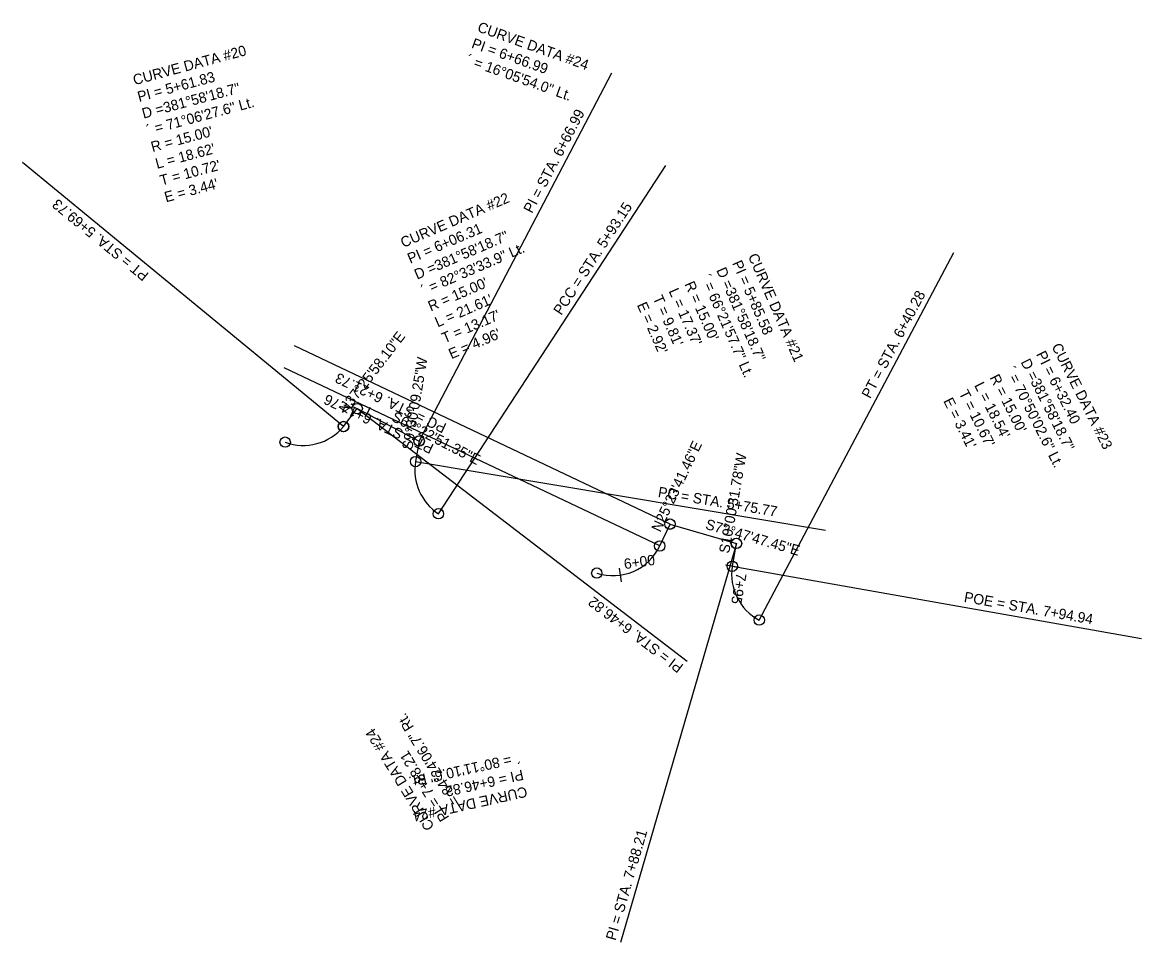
# Model space of a CAD drawing. Extents: x 1158784 to 1165006, y 610007 to 611539.
# Drawn here: x 1158783.8 to 1159106.9, y 611273.6 to 611539.2 of the extents above; entities that cross this region are included whole.
import ezdxf

# ---------------------------------------------------------------- set-up
doc = ezdxf.new("R2010")
doc.units = 0
for name, color, linetype in [('D_Roadway_Centerline', 7, 'Continuous'), ('D_Roadway_Centerline_Bearings', 7, 'Continuous'), ('D_Roadway_Centerline_CurveData', 7, 'Continuous'), ('D_Roadway_Centerline_Flags', 7, 'Continuous'), ('D_Roadway_Centerline_Text', 7, 'Continuous')]:
    doc.layers.add(name, color=color, linetype=linetype)

msp = doc.modelspace()

# ---------------------------------------------------------------- linework, layer by layer
at = {"layer": 'D_Roadway_Centerline'}
for p, q in [((1158876.47, 611422.53), (1158880.44, 611427.72)), ((1158880.44, 611427.72), (1158898.32, 611418.36)), ((1158898.29, 611418.38), (1158897.3, 611412.42)), ((1158967.77, 611388.06), (1158970.76, 611394.36)), ((1158970.72, 611394.39), (1158989.92, 611388.8)), ((1158989.85, 611388.82), (1158988.69, 611382.2))]:
    msp.add_line(p, q, dxfattribs=at)
for centre, start, end in [((1158864.91, 611432.09), 249.4733, 320.581), ((1158912.09, 611409.94), 170.4974, 236.8635), ((1158954.22, 611394.5), 252.0457, 334.6052), ((1159003.51, 611379.93), 171.2886, 242.1227)]:
    msp.add_arc(centre, 15, start, end, dxfattribs=at)
at = {"layer": 'D_Roadway_Centerline_Flags'}
for points in [[(1158898.32, 611418.36), (1158953.95, 611524.69)], [(1158876.5, 611422.56), (1158783.8, 611498.76)], [(1158903.89, 611397.38), (1158969.49, 611497.87)], [(1158996.5, 611366.67), (1159052.61, 611472.74)], [(1158970.76, 611394.36), (1158862.36, 611445.83)], [(1158967.77, 611388.06), (1158859.37, 611439.53)], [(1158880.44, 611427.72), (1158975.73, 611354.78)], [(1158897.3, 611412.42), (1159015.65, 611392.61)], [(1158989.92, 611388.8), (1158956.44, 611273.57)], [(1158988.69, 611382.2), (1159106.86, 611361.35)]]:
    msp.add_lwpolyline(points, dxfattribs=at)
for centre in [(1158880.44, 611427.72), (1158876.47, 611422.53), (1158876.5, 611422.56), (1158859.65, 611418.04), (1158898.29, 611418.38), (1158898.32, 611418.36), (1158897.3, 611412.42), (1158903.89, 611397.38), (1158970.72, 611394.39), (1158970.76, 611394.36), (1158967.77, 611388.06), (1158989.85, 611388.82), (1158989.92, 611388.8), (1158949.6, 611380.23), (1158988.69, 611382.2), (1158988.69, 611382.2), (1158996.5, 611366.67)]:
    msp.add_circle(centre, 1.5, dxfattribs=at)
at = {"layer": 'D_Roadway_Centerline_Text'}
for points in [[(1158884.19, 611428.01), (1158883.27, 611426.24)], [(1158990.65, 611381.85), (1158986.72, 611382.55)], [(1158956.08, 611381.63), (1158956.65, 611377.67)]]:
    msp.add_lwpolyline(points, dxfattribs=at)

# ---------------------------------------------------------------- texts
at = {"layer": 'D_Roadway_Centerline_Bearings'}
for s, rotation, p in [('N37%%d25\'58.10"E', 52.5672, (1158877.27, 611426.03)), ('S9%%d30\'09.25"W', 80.4974, (1158896.31, 611415.65)), ('S62%%d22\'51.35"E', 332.3809, (1158890.08, 611424.37)), ('N25%%d23\'41.46"E', 64.6052, (1158967.91, 611391.86)), ('S10%%d00\'31.78"W', 79.9912, (1158987.79, 611385.77)), ('S73%%d47\'47.45"E', 343.7965, (1158980.74, 611393.04))]:
    msp.add_text(s, height=3, rotation=rotation, dxfattribs=at).set_placement(p)
at = {"layer": 'D_Roadway_Centerline_CurveData'}
for s, rotation, p in [('CURVE DATA #24', 340.4301, (1158914.9, 611536.64)), ('PI = 6+66.99', 340.4301, (1158913.22, 611531.93)), ('CURVE DATA #20', 15.0271, (1158816.18, 611521.06)), ('´ = 16%%d05\'54.0" Lt.', 340.4301, (1158911.55, 611527.22)), ('PI = 5+61.83', 15.0271, (1158817.48, 611516.23)), ('D =381%%d58\'18.7"', 15.0271, (1158818.77, 611511.4)), ('´ = 71%%d06\'27.6" Lt.', 15.0271, (1158820.07, 611506.57)), ("R = 15.00'", 15.0271, (1158821.36, 611501.74)), ("L = 18.62'", 15.0271, (1158822.66, 611496.91)), ("T = 10.72'", 15.0271, (1158823.96, 611492.08)), ("E = 3.44'", 15.0271, (1158825.25, 611487.25)), ('CURVE DATA #22', 23.3254, (1158893.76, 611474.1)), ('PI = 6+06.31', 23.3254, (1158895.74, 611469.51)), ('D =381%%d58\'18.7"', 23.3254, (1158897.72, 611464.92)), ('´ = 82%%d33\'33.9" Lt.', 23.3254, (1158899.7, 611460.33)), ('CURVE DATA #21', 293.6804, (1158993.18, 611471.72)), ('PI = 5+85.58', 293.6804, (1158988.61, 611469.71)), ("R = 15.00'", 23.3254, (1158901.68, 611455.74)), ('´ = 66%%d21\'57.7" Lt.', 293.6804, (1158979.45, 611465.69)), ('D =381%%d58\'18.7"', 293.6804, (1158984.03, 611467.7)), ("L = 17.37'", 293.6804, (1158970.29, 611461.68)), ("R = 15.00'", 293.6804, (1158974.87, 611463.68)), ("L = 21.61'", 23.3254, (1158903.66, 611451.14)), ("T = 9.81'", 293.6804, (1158965.71, 611459.67)), ("T = 13.17'", 23.3254, (1158905.64, 611446.55)), ("E = 2.92'", 293.6804, (1158961.13, 611457.66)), ("E = 4.96'", 23.3254, (1158907.62, 611441.96)), ('CURVE DATA #23', 296.7057, (1159080.8, 611445.68)), ('PI = 6+32.40', 296.7057, (1159076.34, 611443.43)), ('´ = 70%%d50\'02.6" Lt.', 296.7057, (1159067.4, 611438.94)), ('D =381%%d58\'18.7"', 296.7057, (1159071.87, 611441.18)), ("R = 15.00'", 296.7057, (1159062.94, 611436.69)), ("T = 10.67'", 296.7057, (1159054, 611432.2)), ("L = 18.54'", 296.7057, (1159058.47, 611434.44)), ("E = 3.41'", 296.7057, (1159049.54, 611429.95)), ('´ = 84%%d24\'06.7" Rt.', 121.5956, (1158911.36, 611312.3)), ('CURVE DATA #24', 121.5956, (1158902.84, 611307.06)), ('PI = 7+88.21', 121.5956, (1158907.1, 611309.68)), ('´ = 80%%d11\'10.6" Rt.', 192.4741, (1158926.99, 611328.43)), ('PI = 6+46.82', 192.4741, (1158928.07, 611323.55)), ('CURVE DATA #24', 192.4741, (1158929.15, 611318.66))]:
    msp.add_text(s, height=3, rotation=rotation, dxfattribs=at).set_placement(p)
at = {"layer": 'D_Roadway_Centerline_Flags'}
for s, rotation, p in [('PI = STA. 6+66.99', 62.3809, (1158930.91, 611483.88)), ('PT = STA. 5+69.73', 140.581, (1158820.52, 611466.64)), ('PCC = STA. 5+93.15', 56.8635, (1158939.36, 611454.46)), ('PT = STA. 6+40.28', 62.1227, (1159028.51, 611430.4)), ('PC = STA. 6+21.73', 154.6052, (1158906.46, 611423.23)), ('PT = STA. 6+14.76', 154.6052, (1158902.78, 611417.26)), ('PC = STA. 5+75.77', 350.4974, (1158967.11, 611402.25)), ('PI = STA. 6+46.82', 142.5672, (1158974.82, 611353.59)), ('POE = STA. 7+94.94', 349.9912, (1159055.43, 611371.95)), ('PI = STA. 7+88.21', 73.7965, (1158955, 611273.99))]:
    msp.add_text(s, height=3, rotation=rotation, dxfattribs=at).set_placement(p)
at = {"layer": 'D_Roadway_Centerline_Text'}
for s, rotation, p in [('6+00', 8.2298, (1158957.64, 611381.35)), ('7+95', 259.9912, (1158989.9, 611380.46))]:
    msp.add_text(s, height=3, rotation=rotation, dxfattribs=at).set_placement(p)

doc.saveas('drawing.dxf')
